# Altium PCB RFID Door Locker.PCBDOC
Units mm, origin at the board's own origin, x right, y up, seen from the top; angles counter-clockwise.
Board outline 386.33 x 171.7 mm, 2 copper layers (TopLayer, BottomLayer); 61 components, 0 nets, 248 pads, 41 vias.
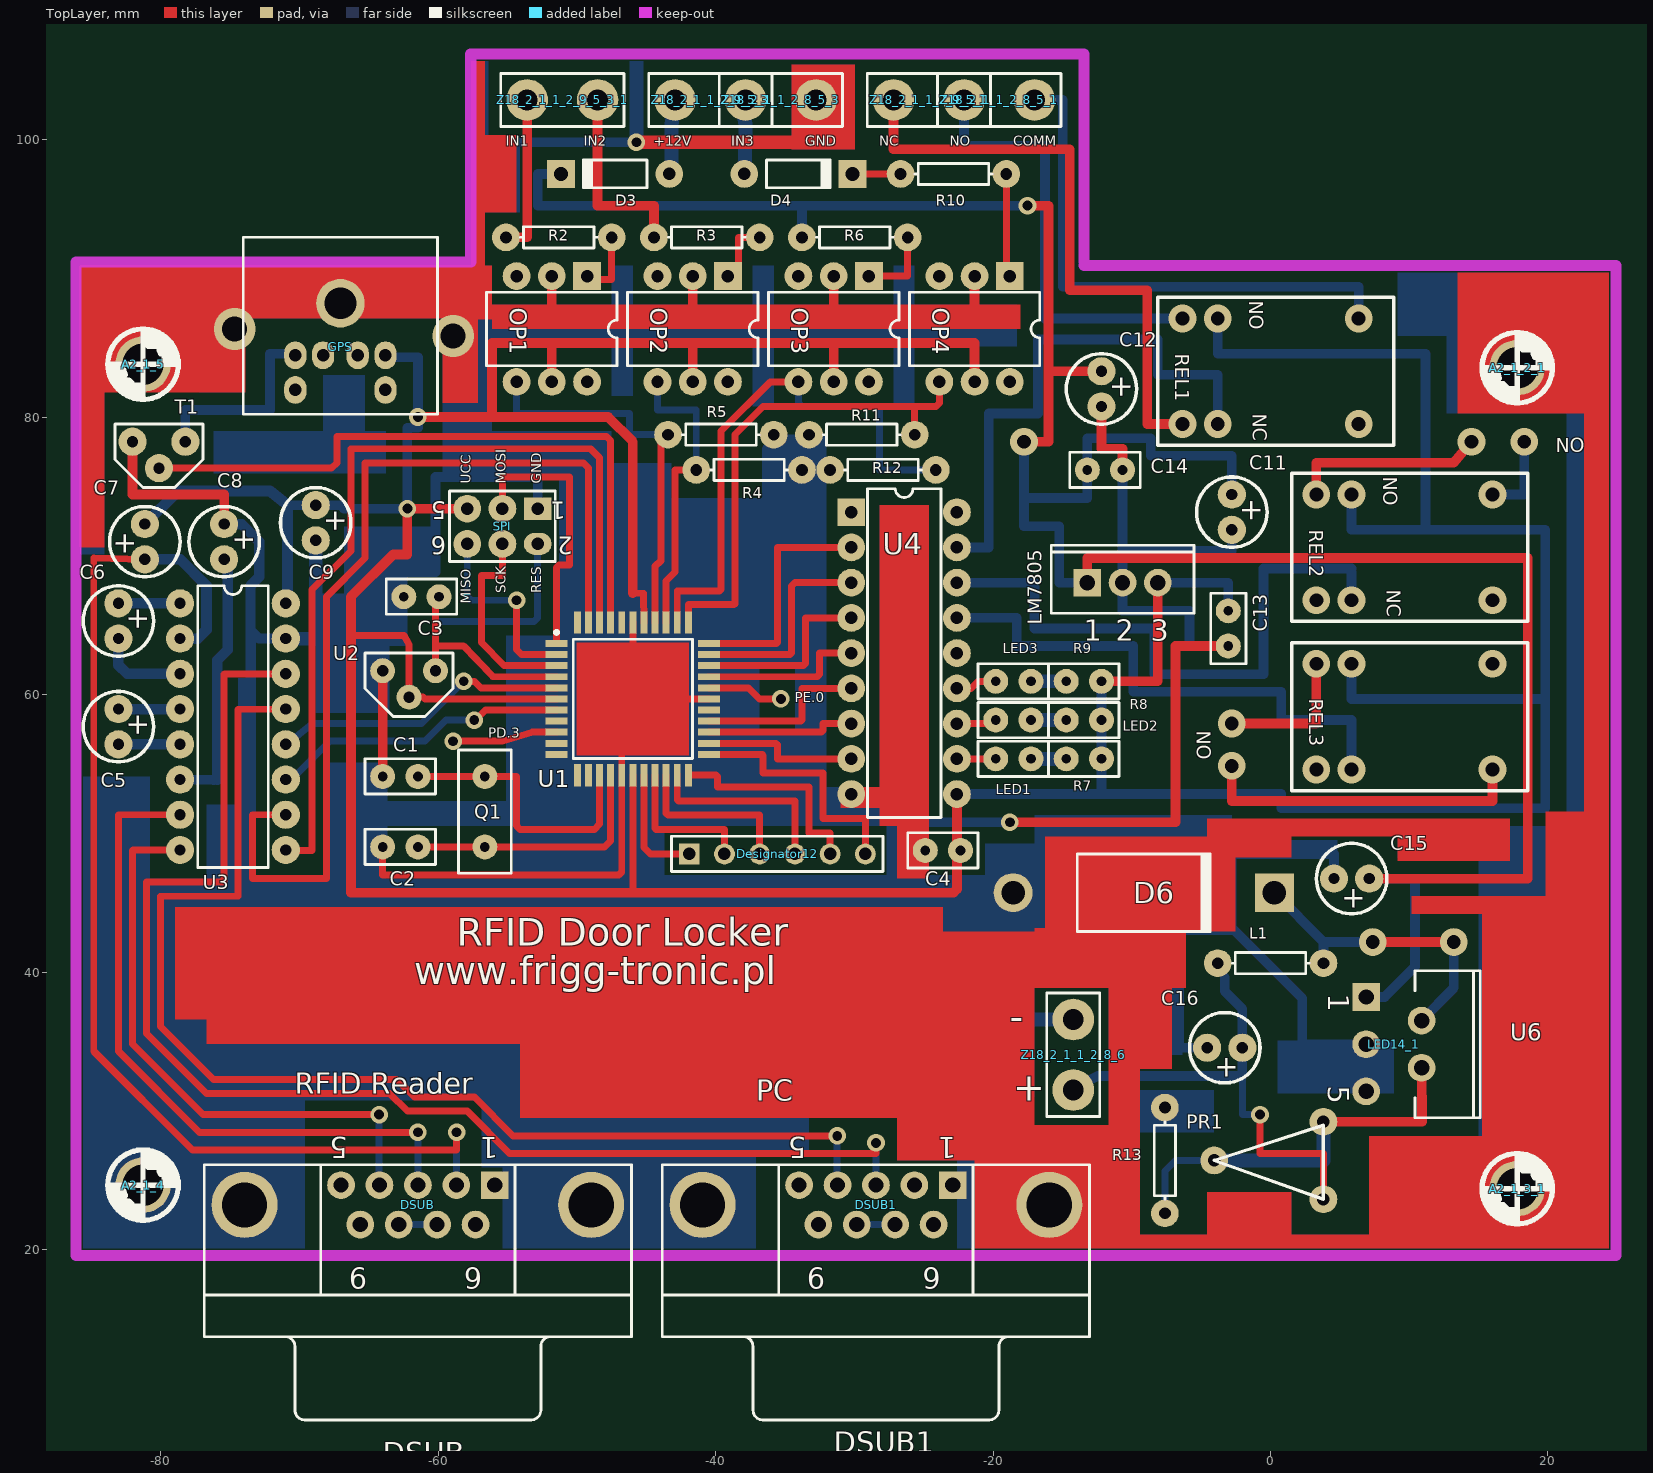
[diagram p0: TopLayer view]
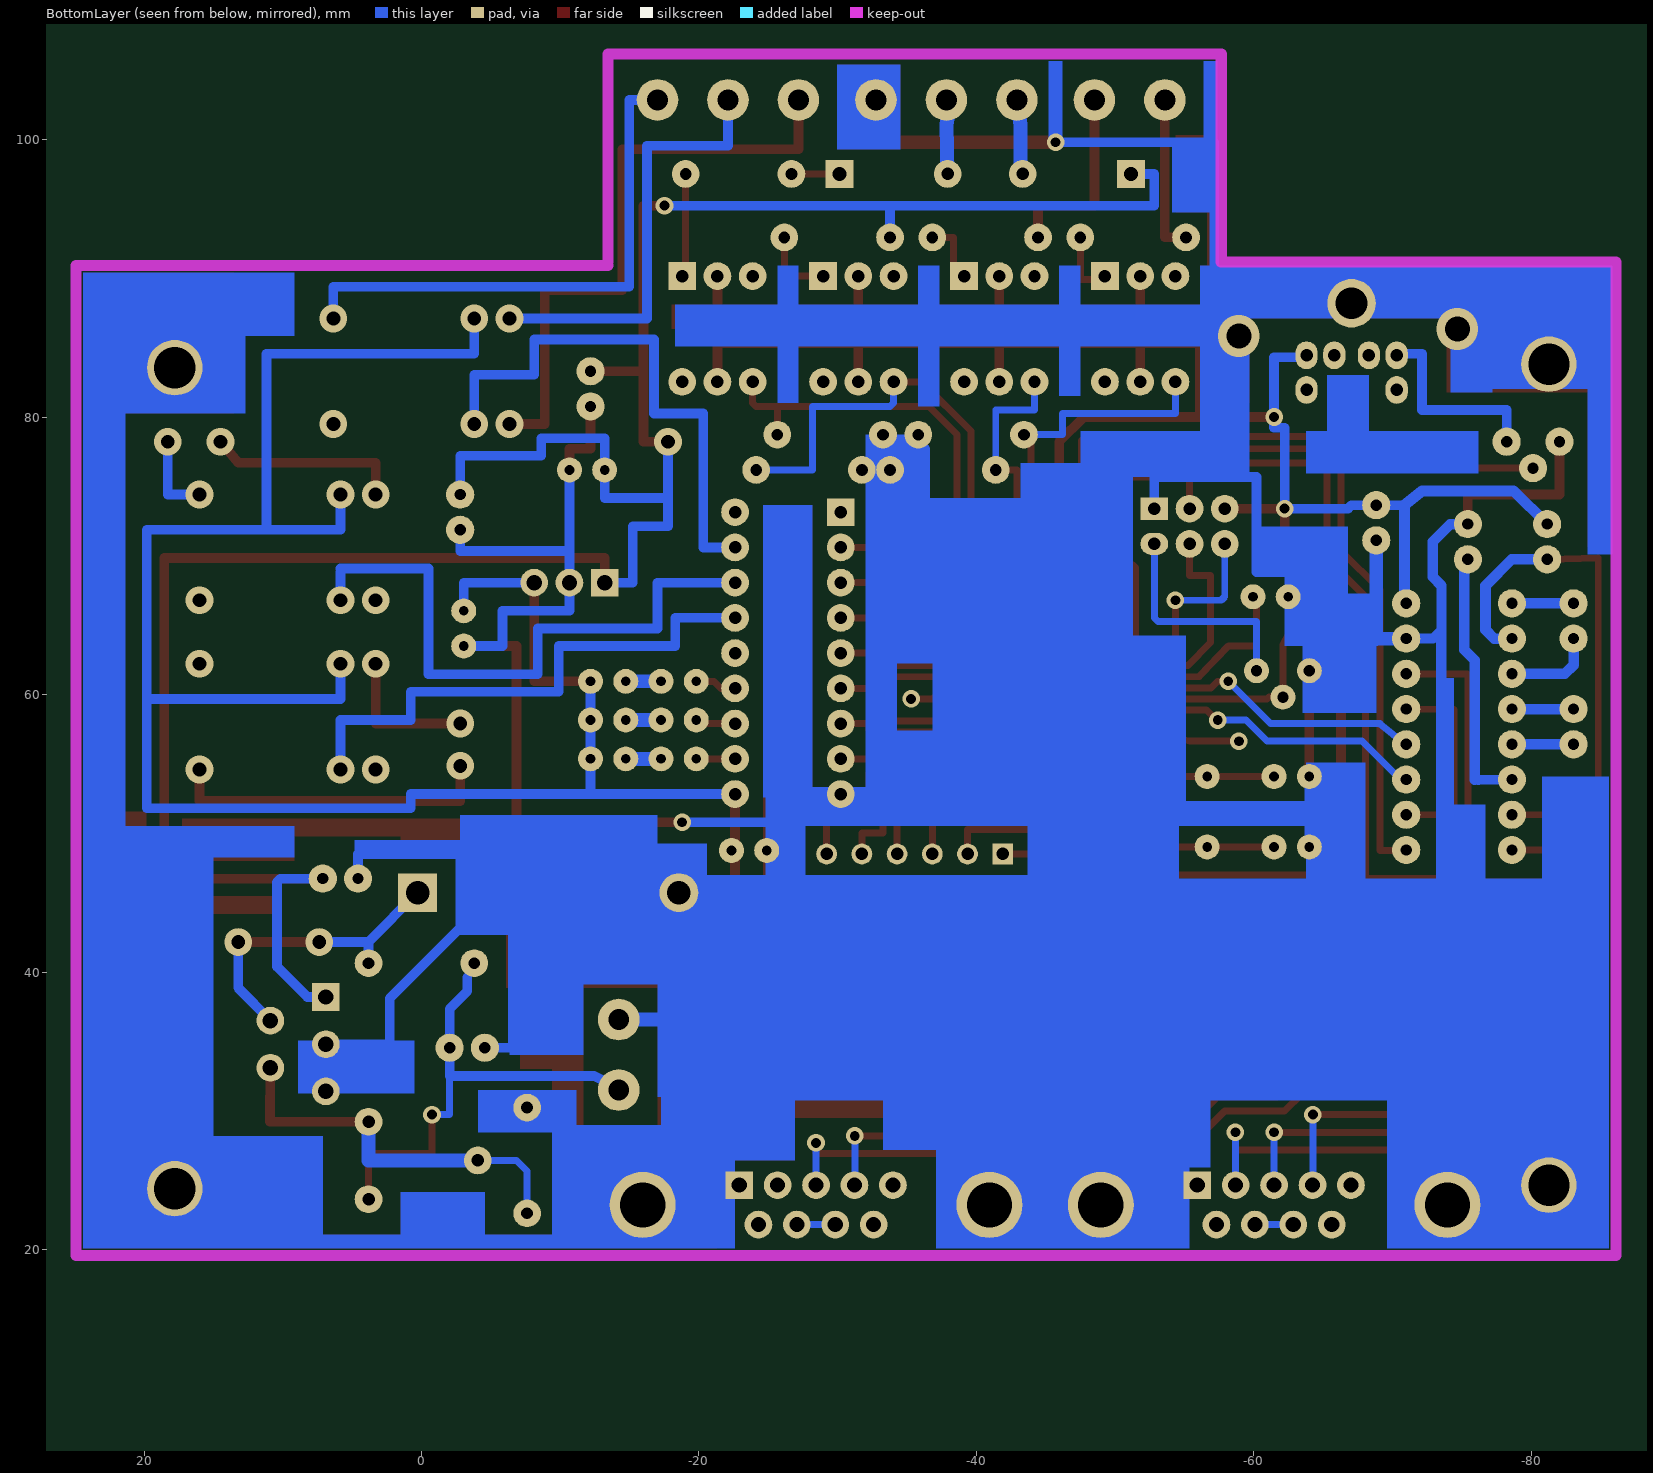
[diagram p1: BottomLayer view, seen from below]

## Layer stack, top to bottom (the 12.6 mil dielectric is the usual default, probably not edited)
TopLayer: signal copper 0.0356
Dielectric: core 0.32, FR-4, Dk 4.8
BottomLayer: signal copper 0.0356

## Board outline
-121.158,136.652 -121.158,-35.052 265.176,-35.052 265.176,136.652

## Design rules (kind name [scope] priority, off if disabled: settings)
Clearance [All] p1: gap=1
ComponentClearance [All] p1: gap=0.254 collisioncheckmode=0
PasteMaskExpansion PasteMaskExpansion_1 [All] p2: expansion=0
PlaneClearance PlaneClearance_1 [All] p1: clearance=0.508
PlaneClearance [All] p2: clearance=0.254
PolygonConnect [All] p1: connectstyle=Relief reliefconductorwidth=0.254 reliefentries=4 polygonreliefangle="90 Angle"
RoutingVias [All] p1: holewidth=1 width=3 viastyle="Through Hole" minholewidth=0.711 minwidth=1.27 maxholewidth=0.711 maxwidth=1.27
ShortCircuit ShortCircuit_1 [All] p2: allowed=FALSE
SolderMaskExpansion SolderMaskExpansion_1 [All] p1: expansion=0.102
SolderMaskExpansion [All] p2: expansion=0.051
TestPointUsage [All] p1: valid=0 allowmultiple=FALSE
Testpoint [All] p1: side=7 testpointundercomponent=TRUE minsize=1.016 maxsize=2.54 preferedsize=1.524 minholesize=0.508 maxholesize=1.016 preferedholesize=0.813 testpointgrid=0.025 style=1001 order=1234567890
UnRoutedNet UnRoutedNet_1 [All] p2:
Width [All] p1: maxlimit=0.8 minlimit=0.1 preferedwidth=0.254 toplayer_maxwidth=0.7 toplayer_prefwidth=0.5 bottomlayer_maxwidth=0.7 bottomlayer_prefwidth=0.5 minimp=50.000000 maximp=50.000000 favimp=50.000000
16 further rules are at their usual default settings.

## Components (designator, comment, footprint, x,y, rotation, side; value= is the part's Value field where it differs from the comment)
A2_1_2_1 "" S2 17.78,83.566 r0 top
A2_1_3_1 "" S2 17.78,24.384 r0 top
A2_1_4 "" S2 -81.28,24.638 r0 top
A2_1_5 "" S2 -81.28,83.82 r0 top
C1 "Comment" RAD-0.1 -61.468,54.102 r180 top
C2 "Comment" RAD-0.1 -61.468,49.022 r180 top
C3 "Comment" RAD-0.1 -59.944,67.056 r180 top
C4 "Comment" RAD-0.1 -22.352,48.768 r180 top
C5 "" CE5#1 -83.058,58.959 r270 top
C6 "" CE5#1 -83.058,66.579 r270 top locked
C7 "" CE5#2 -81.153,69.754 r270 top
C8 "" CE5#1 -75.438,72.294 r270 top locked
C9 "" CE5#1 -68.834,73.66 r270 top
C11 "" CE5#2 -2.794,74.422 r90 top
C12 "" CE5#2 -12.192,83.312 r90 top
C13 "Comment" RAD-0.1 -3.048,66.04 r270 top
C14 "Comment" RAD-0.1 -10.668,76.2 r180 top
C15 "" CE5#1 7.112,46.736 r180 top
C16 "" CE5#1 -2.032,34.544 r180 top
D3 "Comment" DIO7.8-4.6x2 -47.244,97.536 r180 top
D4 "Comment" DIO7.8-4.6x2 -34.036,97.536 r0 top
D6 "Comment" DIO18.84-9.6x5.6 -9.144,45.72 r0 top
Designator12 "Comment" HDR1X6 -41.91,48.514 r0 top
DSUB "Comment" DSUB1.385-2H9 -61.468,13.716 r180 top
DSUB1 "Comment" DSUB1.385-2H9 -28.448,13.716 r180 top
GPS "Comment" PS2-6PIN -67.056,92.964 r0 top
L1 "Comment" AXIAL-0.3 0,40.64 r0 top
LED1 "Comment" RAD-0.1 -17.272,55.372 r180 top
LED2 "Comment" RAD-0.1 -17.272,58.166 r180 top
LED3 "Comment" RAD-0.1 -17.272,60.96 r180 top
LED14_1 "Comment" T05D 8.89,34.798 r270 top
LM7805 "Comment" SFM-T3/X1.6V -10.668,68.072 r0 top
OP1 "Comment" DIP-6 -51.816,86.36 r180 top
OP2 "Comment" DIP-6 -41.656,86.36 r180 top
OP3 "Comment" DIP-6 -31.496,86.36 r180 top
OP4 "Comment" DIP-6 -21.336,86.36 r180 top
Q1 "Comment" RAD-0.2#1 -56.642,54.102 r270 top
R2 "Comment" AXIAL-0.3 -51.308,92.964 r0 top
R3 "Comment" AXIAL-0.3 -40.64,92.964 r0 top
R4 "Comment" AXIAL-0.3 -37.592,76.2 r0 top
R5 "Comment" AXIAL-0.3 -39.624,78.74 r0 top
R6 "Comment" AXIAL-0.3 -29.972,92.964 r0 top
R7 "Comment" RAD-0.1 -12.192,55.372 r180 top
R8 "Comment" RAD-0.1 -12.192,58.166 r180 top
R9 "Comment" RAD-0.1 -12.192,60.96 r180 top
R10 "Comment" AXIAL-0.3 -22.86,97.536 r0 top
R11 "Comment" AXIAL-0.3 -29.464,78.74 r0 top
R12 "Comment" AXIAL-0.3 -27.94,76.2 r180 top
R13 "Comment" AXIAL-0.3 -7.62,26.416 r90 top
SPI "Comment" HDR2X3 -52.832,73.406 r180 top
T1 "" T#1 -82.042,78.232 r0 top
U1 "Comment" 44A -45.974,59.69 r0 top
U2 "" T#2 -64.008,61.722 r0 top
U3 "" U16 -78.613,66.579 r270 top locked
U4 "Comment" DIP-18 -26.416,62.992 r270 top
Z18_2_1_1_2_8_5_1 "Comment" RAD-0.2#2 -17.018,102.87 r180 top
Z18_2_1_1_2_8_5_3 "Comment" RAD-0.2#2 -32.766,102.87 r180 top
Z18_2_1_1_2_8_6 "Comment" RAD-0.2#2 -14.224,36.576 r270 top
Z18_2_1_1_2_9_5_1 "Comment" RAD-0.2#2 -22.098,102.87 r180 top
Z18_2_1_1_2_9_5_3 "Comment" RAD-0.2#2 -37.846,102.87 r180 top
Z18_2_1_1_2_9_5_3_1 "Comment" RAD-0.2#2 -48.514,102.87 r180 top

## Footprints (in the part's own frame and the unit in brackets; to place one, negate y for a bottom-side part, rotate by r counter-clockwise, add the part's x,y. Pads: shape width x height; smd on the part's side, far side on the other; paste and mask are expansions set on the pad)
44A [mm] "QFP; 44 Leads; Body 10 x 10 mm; Pitch 0.8 mm"
  rect 1.6x0.5 smd: 1(-5.5,4) 2(-5.5,3.2) 3(-5.5,2.4) 4(-5.5,1.6) 5(-5.5,0.8) 6(-5.5,0) 7(-5.5,-0.8) 8(-5.5,-1.6) 9(-5.5,-2.4) 10(-5.5,-3.2) 11(-5.5,-4) 23(5.5,-4) 24(5.5,-3.2) 25(5.5,-2.4) 26(5.5,-1.6) 27(5.5,-0.8) 28(5.5,0) 29(5.5,0.8) 30(5.5,1.6) 31(5.5,2.4) 32(5.5,3.2) 33(5.5,4)
  rect 0.5x1.6 smd: 12(-4,-5.5) 13(-3.2,-5.5) 14(-2.4,-5.5) 15(-1.6,-5.5) 16(-0.8,-5.5) 17(0,-5.5) 18(0.8,-5.5) 19(1.6,-5.5) 20(2.4,-5.5) 21(3.2,-5.5) 22(4,-5.5) 34(4,5.5) 35(3.2,5.5) 36(2.4,5.5) 37(1.6,5.5) 38(0.8,5.5) 39(0,5.5) 40(-0.8,5.5) 41(-1.6,5.5) 42(-2.4,5.5) 43(-3.2,5.5) 44(-4,5.5)
  silkscreen extent -5.62,-4.3 4.3,4.92
AXIAL-0.3 [mm]
  round 2 hole 0.85: 1(-3.81,0) 2(3.81,0)
  silkscreen extent -2.77,-0.76 2.77,0.76
CE5#1 [mil]
  round 80 hole 32: 1(0,0) 2(100,0)
  silkscreen extent -50,-100 150,100
CE5#2 [mil]
  round 80 hole 32: 1(0,0) 2(-100,0)
  silkscreen extent -150,-100 50,100
DIO7.8-4.6x2 [mm]
  round 2 hole 0.9: 1(-3.9,0)
  rect 2x2 hole 1: 2(3.9,0)
  silkscreen extent -2.3,-1 2.4,1
DIO18.84-9.6x5.6 [mm]
  round 2.8 hole 1.7: 1(-9.42,0)
  rect 2.8x2.8 hole 1.7: 2(9.42,0)
  silkscreen extent -4.8,-2.8 4.9,2.8
DIP-6 [mm]
  rect 2x2 hole 0.9: 1(-2.54,-3.81)
  round 2 hole 0.9: 2(0,-3.81) 3(2.54,-3.81) 4(2.54,3.81) 5(0,3.81) 6(-2.54,3.81)
  silkscreen extent -4.7,-2.65 4.7,2.65
DIP-18 [mm]
  rect 2x2 hole 0.9: 1(-10.16,-3.81)
  round 2 hole 0.9: 2(-7.62,-3.81) 3(-5.08,-3.81) 4(-2.54,-3.81) 5(0,-3.81) 6(2.54,-3.81) 7(5.08,-3.81) 8(7.62,-3.81) 9(10.16,-3.81) 10(10.16,3.81) 11(7.62,3.81) 12(5.08,3.81) 13(2.54,3.81) 14(0,3.81) 15(-2.54,3.81) 16(-5.08,3.81) 17(-7.62,3.81) 18(-10.16,3.81)
  silkscreen extent -11.85,-2.65 11.85,2.65
DSUB1.385-2H9 [mm] "Connector; D Subminiature; 9 Position; Right Angle; Pitch 1.385 mm"
  round 2 hole 1.09: 1(5.54,-10.92) 2(2.77,-10.92) 3(0,-10.92) 4(-2.77,-10.92) 6(4.155,-8.08) 7(1.385,-8.08) 8(-1.385,-8.08) 9(-4.155,-8.08)
  rect 2x2 hole 1.09 unplated: 5(-5.54,-10.92)
  round 4.76 hole 3.26: 10(-12.495,-9.5) 11(12.495,-9.5)
  silkscreen extent -15.4,-12.4 15.4,6
HDR1X6 [mm] "Connector; Header; 6 Position"
  rect 1.5x1.5 hole 0.9: 1(0,0)
  round 1.5 hole 0.9: 2(2.54,0) 3(5.08,0) 4(7.62,0) 5(10.16,0) 6(12.7,0)
  silkscreen extent -1.27,-1.27 13.97,1.27
HDR2X3 [mm]
  rect 2x1.6 hole 0.9: 1(0,0)
  oval 2x1.6 hole 0.9: 2(0,2.54)
  round 2 hole 0.9: 3(2.54,0) 4(2.54,2.54) 5(5.08,0) 6(5.08,2.54)
  silkscreen extent -1.27,-1.27 6.35,3.81
PS2-6PIN [mm] "PS2 Socket, 6 Pin, Through Hole"
  oval 1.6x2 hole 0.9: 1(-1.25,-8.5) 2(1.25,-8.5) 3(-3.25,-8.5) 4(3.25,-8.5) 5(-3.25,-11) 6(3.25,-11)
  round 3.5 hole 2.3: S(0,-4.75)
  silkscreen extent -7,-12.75 7,0
RAD-0.1 [mm]
  round 1.8 hole 0.7: 1(0,0) 2(2.54,0)
  silkscreen extent -1.27,-1.27 3.81,1.27
RAD-0.2#1 [mm]
  round 1.8 hole 0.7: 1(0,0) 2(5.08,0)
  silkscreen extent -1.91,-1.91 6.98,1.91
RAD-0.2#2 [mm]
  round 3 hole 1.5: 1(0,0) 2(5.08,0)
  silkscreen extent -1.91,-1.91 6.98,1.91
S2 [mm]
  round 4 hole 2.972: 0(0,0)
  silkscreen extent -2.54,-2.54 2.54,2.54
SFM-T3/X1.6V [mm]
  rect 2x2 hole 1.1: 1(-2.54,0)
  round 2 hole 1.1: 2(0,0) 3(2.54,0)
  silkscreen extent -5.15,-2.2 5.15,2.7
T#1 [mil]
  round 80 hole 32: 1(0,0) 2(75,-75) 3(150,0)
  silkscreen extent -50,-130 200,50
T#2 [mil]
  round 70.87 hole 32: 1(0,0) 2(75,-75) 3(150,0)
  silkscreen extent -50,-130 200,50
T05D [mm] "TO, Thru-Hole, Vertical, Heatsink Mounted; 5 Bent Staggered Leads; Pitch 1.7 mm"
  rect 2x2 hole 1.1: 1(-3.4,-2)
  round 2 hole 1.1: 2(-1.7,2) 3(0,-2) 4(1.7,2) 5(3.4,-2)
  silkscreen extent -5.3,1.53 5.3,6.23
U16 [mil]
  round 80 hole 32: 1(0,0) 2(100,0) 3(200,0) 4(300,0) 5(400,0) 6(500,0) 7(600,0) 8(700,0) 9(700,300) 10(600,300) 11(500,300) 12(400,300) 13(300,300) 14(200,300) 15(100,300) 16(0,300)
  silkscreen extent -50,50 750,250

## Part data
D6: library part "Diode 1N5402"
Designator12: library part "Header 6"
DSUB DSUB1: library part "D Connector 9"
GPS: library part PS2-6PIN
LED14_1: library part LM2576HVT-5.0LB03
LM7805: library part Diac-NPN
SPI: library part "Header 3X2"
U1: library part ATmega162-16AC

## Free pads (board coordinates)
  round 2 hole 1: 0(7.366,42.164) 0(13.208,42.164)
  round 2 hole 0.9: 9(-4.064,26.416) 10(3.81,29.21) 11(3.81,23.622)

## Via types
v1: diameter 2, hole 1, TopLayer to BottomLayer, 23 vias
v2: diameter 1.27, hole 0.711, TopLayer to BottomLayer, 16 vias
v3: diameter 3, hole 1.8, TopLayer to BottomLayer, 2 vias

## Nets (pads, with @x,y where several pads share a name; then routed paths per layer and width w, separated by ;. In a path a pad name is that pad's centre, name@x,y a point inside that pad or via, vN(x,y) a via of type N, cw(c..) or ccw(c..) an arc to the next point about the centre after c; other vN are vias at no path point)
pads on no net: A2_1_2_1.0 A2_1_3_1.0 A2_1_4.0 A2_1_5.0 C1.1 C1.2 C2.1 C2.2 C3.1 C3.2 C4.1 C4.2 C5.1 C5.2 C6.1 C6.2 C7.1 C7.2 C8.1 C8.2 C9.1 C9.2 C11.1 C11.2 C12.1 C12.2 C13.1 C13.2 C14.1 C14.2 C15.1 C15.2 C16.1 C16.2 D3.1 D3.2 D4.1 D4.2 D6.1 D6.2 Designator12.1 Designator12.2 Designator12.3 Designator12.4 Designator12.5 Designator12.6 DSUB1.1 DSUB1.2 DSUB1.3 DSUB1.4 DSUB1.5 DSUB1.6 DSUB1.7 DSUB1.8 DSUB1.9 DSUB1.10 DSUB1.11 DSUB.1 DSUB.2 DSUB.3 DSUB.4 DSUB.5 DSUB.6 DSUB.7 DSUB.8 DSUB.9 DSUB.10 DSUB.11 GPS.1 GPS.2 GPS.3 GPS.4 GPS.5 GPS.6 GPS.S L1.1 L1.2 LED1.1 LED1.2 LED2.1 LED2.2 LED3.1 LED3.2 LED14_1.1 LED14_1.2 LED14_1.3 LED14_1.4 LED14_1.5 LM7805.1 LM7805.2 LM7805.3 OP1.1 OP1.2 OP1.3 OP1.4 OP1.5 OP1.6 OP2.1 OP2.2 OP2.3 OP2.4 OP2.5 OP2.6 OP3.1 OP3.2 OP3.3 OP3.4 OP3.5 OP3.6 OP4.1 OP4.2 OP4.3 OP4.4 OP4.5 OP4.6 Q1.1 Q1.2 R2.1 R2.2 R3.1 R3.2 R4.1 R4.2 R5.1 R5.2 R6.1 R6.2 R7.1 R7.2 R8.1 R8.2 R9.1 R9.2 R10.1 R10.2 R11.1 R11.2 R12.1 R12.2 R13.1 R13.2 SPI.1 SPI.2 SPI.3 SPI.4 SPI.5 SPI.6 T1.1 T1.2 T1.3 U1.1 U1.2 U1.3 U1.4 U1.5 U1.6 U1.7 U1.8 U1.9 U1.10 U1.11 U1.12 U1.13 U1.14 U1.15 U1.16 U1.17 U1.18 U1.19 U1.20 U1.21 U1.22 U1.23 U1.24 U1.25 U1.26 U1.27 U1.28 U1.29 U1.30 U1.31 U1.32 U1.33 U1.34 U1.35 U1.36 U1.37 U1.38 U1.39 U1.40 U1.41 U1.42 U1.43 U1.44 U2.1 U2.2 U2.3 U3.1 U3.2 U3.3 U3.4 U3.5 U3.6 U3.7 U3.8 U3.9 U3.10 U3.11 U3.12 U3.13 U3.14 U3.15 U3.16 U4.1 U4.2 U4.3 U4.4 U4.5 U4.6 U4.7 U4.8 U4.9 U4.10 U4.11 U4.12 U4.13 U4.14 U4.15 U4.16 U4.17 U4.18 Z18_2_1_1_2_8_5_1.1 Z18_2_1_1_2_8_5_1.2 Z18_2_1_1_2_8_5_3.1 Z18_2_1_1_2_8_5_3.2 Z18_2_1_1_2_8_6.1 Z18_2_1_1_2_8_6.2 Z18_2_1_1_2_9_5_1.1 Z18_2_1_1_2_9_5_1.2 Z18_2_1_1_2_9_5_3.1 Z18_2_1_1_2_9_5_3.2 Z18_2_1_1_2_9_5_3_1.1 Z18_2_1_1_2_9_5_3_1.2
copper on no net: | length 2482.1
  TopLayer w0.5: -81.153,69.754 -84.836,69.85 -84.836,47.752 -84.836,46.736 -84.836,34.29 -77.724,27.178 -58.674,27.178 v2(-58.674,28.448) ; -80.137,76.327 -68.199,76.327 -67.691,76.327 -67.31,76.708 -67.31,78.613 -47.879,78.613 -47.574,78.308 -47.574,65.19 ; -78.613,48.799 -82.011,48.799 -82.042,48.768 -82.042,34.798 -76.962,29.718 v2(-64.262,29.718) ; -78.613,51.339 -83.027,51.339 -83.058,51.308 -83.058,34.29 -77.216,28.448 v2(-61.468,28.448) ; -70.993,48.799 -70.358,48.768 -69.088,48.768 -69.088,49.53 -69.088,51.816 -69.088,67.564 -66.294,70.358 -66.294,71.12 -66.294,77.724 -54.864,77.724 ; -70.993,51.339 -73.375,51.339 -73.406,51.308 -73.406,46.736 -73.152,46.736 -68.072,46.736 -68.072,47.752 -68.072,55.372 -68.072,67.056 -65.278,69.85 -65.278,71.12 -65.278,76.708 -49.53,76.708 -49.174,76.352 -49.174,65.19 ; -70.993,58.959 -74.422,58.928 -74.422,55.626 -74.422,45.466 -80.01,45.466 -80.01,36.068 -76.2,32.258 -62.992,32.258 -61.722,30.988 -57.404,30.988 -54.61,28.194 v2(-31.242,28.194) ; -70.993,61.499 -75.407,61.499 -75.438,61.468 -75.438,46.482 -81.026,46.482 -81.026,35.56 -76.708,31.242 -63.5,31.242 -62.23,29.972 -57.912,29.972 -54.864,26.924 -28.448,26.924 v2(-28.448,27.686) ; -66.294,64.262 -62.738,64.262 -62.484,64.262 -62.103,63.627 -62.103,59.817 -61.087,59.817 -60.96,59.69 -59.182,59.69 -51.474,59.69 ; -64.008,49.022 -64.008,46.99 -54.864,46.99 -46.99,46.99 -46.774,47.206 -46.774,47.282 -46.774,51.854 -46.774,54.19 -46.774,55.842 ; -61.722,49.022 -56.642,49.022 -48.006,49.022 -47.574,49.454 -47.574,50.622 -47.574,54.19 ; -61.468,54.102 -56.642,54.102 -55.118,54.102 -54.356,54.102 -54.356,50.546 -54.102,50.292 -48.742,50.292 -48.374,50.66 -48.374,54.19 ; -60.198,61.722 -60.198,63.754 -60.198,64.262 -60.198,66.294 -59.944,67.056 ; -60.198,63.5 -58.166,63.5 -56.134,61.366 -56.058,61.29 -51.474,61.29 ; v2(-58.928,56.642) -55.372,56.642 -53.226,57.29 -51.474,57.29 ; v3(-58.928,85.852) v3@-57.912,85.852 ; v2(-58.166,60.96) -57.404,60.96 -56.934,60.49 -51.474,60.49 ; v2(-57.404,58.166) -57.328,58.166 -56.604,58.89 -51.474,58.89 ; -55.372,70.866 -55.372,68.58 -56.896,68.58 -56.896,66.04 -56.896,63.754 -55.258,62.09 -51.474,62.09 ; -55.372,73.406 -55.372,75.692 -50.546,75.692 -50.546,69.342 -51.308,69.342 -51.474,69.176 -51.474,63.69 ; -55.118,77.724 -49.022,77.724 -48.374,77.076 -48.374,76.314 -48.374,65.19 ; v2(-54.356,66.802) -54.356,63.246 -54,62.89 -51.474,62.89 ; -49.022,89.916 -48.514,89.916 -47.498,89.916 -47.498,90.932 -47.498,92.964 ; -45.974,45.72 -45.974,54.19 ; -45.974,63.246 -45.974,65.19 ; -45.974,67.31 -45.212,67.31 -45.174,65.19 ; -45.174,54.19 -45.174,48.984 -44.704,48.514 -41.91,48.514 ; -44.374,54.19 -44.374,50.368 -44.298,50.292 -39.37,50.292 -39.37,48.514 ; -44.374,65.19 -44.374,69.266 -43.942,69.646 -43.942,78.74 ; -43.574,54.19 -43.574,51.448 -43.434,51.308 -36.83,51.308 -36.83,48.514 ; -43.574,65.19 -43.574,68.186 -42.926,68.834 -42.926,73.152 -42.926,76.2 -41.402,76.2 ; -43.344,97.192 -43.344,97.536 ; -42.774,54.19 -42.774,52.426 -42.672,52.324 -34.29,52.324 -34.29,48.514 ; -42.774,65.19 -42.774,67.208 -42.774,67.462 -39.726,67.462 ; -42.164,59.69 -40.474,59.69 ; -41.974,54.19 -39.966,54.19 -39.878,54.102 -39.878,53.34 -33.274,53.34 -33.274,50.038 -31.75,50.038 -31.75,48.514 -31.838,48.602 ; -41.974,65.19 -41.974,66.484 -38.672,66.484 -38.608,66.548 -38.608,69.85 -38.608,72.136 -38.608,78.74 -36.576,80.772 -24.13,80.772 -23.876,81.026 -23.876,82.55 ; -40.474,55.69 -38.164,55.69 -36.64,55.69 -36.576,55.626 -36.576,54.356 -32.258,54.356 -32.258,51.054 -29.21,51.054 -29.21,48.514 ; -40.474,56.49 -35.662,56.49 -35.56,56.388 -35.56,55.372 -30.226,55.372 ; -40.474,57.29 -32.372,57.29 -32.258,57.404 -32.258,57.912 -30.226,57.912 ; -40.474,58.09 -33.858,58.09 -33.782,58.166 -33.782,60.452 -33.274,60.452 -30.226,60.452 ; -40.474,60.49 -37.63,60.49 -36.83,59.69 v2(-35.306,59.69) ; -40.474,61.29 -32.69,61.29 -32.512,61.468 -32.512,62.992 -30.226,62.992 ; -40.474,62.09 -36.97,62.09 -33.668,62.09 -33.528,62.23 -33.528,65.532 -30.226,65.532 ; -40.474,62.89 -34.646,62.89 -34.544,62.992 -34.544,67.818 -34.29,68.072 -30.226,68.072 ; -40.474,63.69 -35.624,63.69 -35.56,63.754 -35.56,70.612 -30.226,70.612 ; -39.624,67.564 -39.624,70.612 -39.624,72.136 -39.624,78.994 -36.068,82.55 -34.036,82.55 ; -38.354,89.916 -38.354,92.964 -37.592,92.964 -36.83,92.964 ; -30.136,97.536 -26.924,97.536 -26.924,97.282 ; -28.956,90.17 -27.432,90.17 -26.162,90.17 -26.162,91.44 -26.162,92.964 ; -25.654,78.74 -25.654,80.772 ; -22.606,55.372 -19.812,55.372 ; -22.606,57.912 -20.066,57.912 -19.812,58.166 ; -22.606,60.452 -21.59,60.452 -21.082,60.96 -19.812,60.96 ; -19.05,97.536 -19.05,94.234 -19.05,91.186 -18.796,90.17 ; v2(-0.762,29.718) -0.762,26.924 3.81,26.924 3.81,23.622
  TopLayer w0.7: -82.042,78.232 -82.042,74.422 -75.438,74.422 -75.438,72.294 ; -64.008,54.102 -64.008,61.722 ; v2(-61.468,80.01) -48.768,80.01 -47.752,80.01 -45.974,78.232 -45.974,67.31 ; v3(-58.928,85.852) -57.912,87.376 -51.816,87.376 ; -57.912,73.406 v2(-62.23,73.406) -62.23,70.104 -63.246,70.104 -66.294,67.056 -66.294,46.736 -66.294,45.72 -45.974,45.72 -22.86,45.72 -22.606,45.974 -22.606,52.832 ; -56.134,80.01 -56.134,85.344 -51.816,85.344 ; -55.118,92.964 -53.594,92.964 -53.594,102.87 ; -51.816,82.55 -51.816,85.344 ; -51.816,90.17 -51.816,87.376 ; -48.514,102.87 -48.514,95.25 -44.45,95.25 -44.45,92.964 ; -41.656,82.55 -41.656,85.344 ; -41.656,90.17 -41.656,87.376 ; -40.894,87.376 -41.656,87.376 ; -31.496,82.55 -31.496,85.344 ; -31.496,90.17 -31.496,87.376 ; -27.178,102.87 -27.178,99.314 -14.478,99.314 -14.478,89.154 -8.89,89.154 -8.89,79.502 v1(-6.35,79.502) ; -21.336,82.55 -21.336,85.344 -31.496,85.344 ; -21.336,90.17 -21.336,87.376 -31.496,87.376 ; v2(-18.796,50.8) -6.858,50.8 -6.858,63.5 -3.048,63.5 ; v1(-17.78,78.232) -16.002,78.232 -16.002,83.312 ; v2(-17.526,95.25) -16.002,95.25 -16.002,88.646 -16.002,83.312 ; -13.208,68.072 -13.208,69.85 8.636,69.85 18.542,69.85 18.542,46.736 7.112,46.736 ; -12.192,60.96 -8.128,60.96 -8.128,68.072 ; -12.192,80.772 -12.192,77.978 -12.192,77.724 -10.668,77.724 -10.668,76.2 ; -12.192,83.312 -16.002,83.312 ; v1(-2.794,54.864) -2.794,52.324 16.002,52.324 v1(16.002,54.61) ; v1(-2.794,57.912) 3.302,57.912 v1(3.302,62.23) ; v1(3.302,74.422) 3.302,76.708 13.208,76.708 v1(14.478,78.232) ; 3.81,29.21 10.922,29.21 10.89,33.098 ; 7.366,42.164 13.208,42.164 ; -51.816,85.344 -41.656,85.344 ; -51.816,87.376 -41.656,87.376 ; -41.656,85.344 -31.496,85.344 ; -41.656,87.376 -31.496,87.376
  TopLayer w1: v2(-45.72,99.822) -32.766,99.822 -32.766,102.87
  BottomLayer w0.5: -70.993,56.419 -70.962,56.388 -69.088,57.912 -64.262,57.912 -61.214,57.912 v2(-58.166,60.96) ; -70.358,54.102 -67.818,56.642 -60.96,56.642 -59.436,58.166 v2(-57.404,58.166) ; -64.262,24.66 v2(-64.262,29.718) ; -62.853,21.796 -60.083,21.796 ; -61.468,24.636 v2(-61.468,28.448) ; -60.198,61.722 -60.198,65.278 -53.086,65.278 -52.832,65.532 -52.832,70.866 ; -58.698,24.636 -58.674,24.66 v2(-58.674,28.448) ; -57.912,70.866 -57.912,67.056 -57.658,66.802 v2(-54.356,66.802) ; -54.356,82.55 -54.356,80.264 -46.228,80.264 -46.228,78.74 -43.942,78.74 ; -44.196,82.55 -44.196,80.518 -41.402,80.518 -41.402,78.74 -41.402,76.2 ; -38.1,102.616 -37.846,102.87 ; -34.036,82.55 -34.036,81.026 -33.782,80.772 -28.194,80.772 -28.194,76.2 -24.13,76.2 ; -31.242,24.66 v2(-31.242,28.194) ; -29.833,21.796 -27.063,21.796 ; -28.448,24.636 v2(-28.448,27.686) ; -7.62,22.098 -7.62,25.654 -6.858,26.416 -4.572,26.416 -4.064,26.416 ; -2.032,32.512 -2.032,29.718 v2(-0.762,29.718)
  BottomLayer w0.7: -81.311,72.136 -81.153,72.294 ; -78.836,51.562 -78.613,51.339 ; -78.613,53.879 -76.2,53.848 ; -78.232,78.232 -78.232,80.518 -72.136,80.518 -72.136,84.582 -71.12,84.582 -70.306,84.464 ; -73.533,67.849 -73.533,64.643 -72.929,64.039 -70.993,64.039 ; -70.993,48.799 -70.866,49.022 ; -70.866,73.66 -68.834,73.66 -67.056,73.66 -66.802,73.406 v2(-62.23,73.406) -62.23,79.248 -61.468,79.248 -61.468,84.328 -63.246,84.328 -63.806,84.464 ; -64.008,49.022 -64.008,54.102 ; -64.008,61.722 -64.008,63.5 ; -62.992,66.802 -62.992,68.834 -60.198,68.834 -60.198,75.692 -52.832,75.692 -52.832,73.406 ; -57.15,90.678 -57.15,99.822 v2(-45.72,99.822) ; -56.896,49.022 -56.582,49.082 ; -51.144,97.536 -52.832,97.536 -52.832,95.25 -33.782,95.25 ; -48.006,71.12 -36.322,71.12 -36.322,73.914 ; -36.322,77.724 -36.322,73.66 -36.322,75.184 -33.782,75.184 -33.782,72.644 ; -33.782,92.964 -33.782,95.25 ; -30.226,52.832 -25.146,52.832 -25.146,51.308 -25.146,46.736 ; -25.146,50.8 v2(-18.796,50.8) ; -22.606,52.832 -12.192,52.832 ; -22.606,65.532 -18.288,65.532 -18.288,63.5 -9.906,63.5 -9.906,60.198 0.762,60.198 0.762,58.166 5.842,58.166 5.842,56.642 v1(5.842,54.61) ; -22.606,68.072 -18.288,68.072 -17.018,68.072 -17.018,64.77 -8.382,64.77 -8.382,61.468 -0.508,61.468 -0.508,69.088 1.016,69.088 5.842,69.088 ; -22.606,70.612 -20.32,70.612 -20.32,80.264 -16.764,80.264 -16.764,85.598 -12.192,85.598 -9.652,85.598 -8.128,85.598 -8.128,83.058 -3.81,83.058 -3.81,81.534 v1(-3.81,79.502) ; -22.098,102.87 -22.098,99.568 -16.256,99.568 -16.256,87.122 v1(-6.35,87.122) ; -18.564,45.72 -7.112,45.72 ; v1(-17.78,78.232) -17.78,74.168 ; v2(-17.526,95.25) -20.828,95.25 -33.782,95.25 ; -17.018,102.87 -14.986,102.87 -14.986,97.79 -14.986,89.408 6.35,89.408 6.35,88.138 ; -13.97,31.75 -12.446,32.512 -2.032,32.512 -2.032,34.544 -2.032,37.338 -3.302,38.608 -3.302,39.624 ; -13.208,68.072 -15.24,68.072 -15.24,72.136 -17.78,72.136 -17.78,73.152 -17.78,74.168 ; -12.192,60.96 -12.192,58.166 -12.192,55.372 -12.192,52.832 ; -10.668,76.2 -10.668,68.072 ; -8.128,68.072 -3.048,68.072 -3.048,66.04 ; -4.572,34.544 -6.604,34.544 -6.604,45.212 -7.112,45.72 ; v1(-3.81,87.122) -3.81,85.344 -3.81,84.582 8.128,84.582 ; -3.048,63.5 -5.842,63.5 -5.842,66.04 -10.668,66.04 -10.668,68.072 ; -2.794,48.514 -2.794,43.18 2.286,38.1 2.286,34.798 6.89,34.798 6.89,31.398 ; -2.794,71.882 -2.794,70.358 -10.668,70.358 -10.668,68.072 ; -2.794,74.422 -2.794,77.216 -6.604,77.216 -8.636,77.216 -8.636,78.486 -13.208,78.486 -13.208,74.168 -17.78,74.168 ; 0.276,45.72 3.81,42.164 ; 4.572,46.736 4.572,47.244 4.572,48.514 -4.318,48.514 -7.112,45.72 ; v1(5.842,62.23) 5.842,60.452 5.842,59.69 17.78,59.69 ; v1(5.842,66.802) 5.842,68.834 ; v1(5.842,74.422) 5.842,72.644 5.842,71.882 17.78,71.882 ; 6.604,84.582 11.176,84.582 11.176,71.882 ; 6.89,38.198 8.226,38.198 10.414,40.386 10.414,44.704 10.414,46.482 10.16,46.736 7.112,46.736 ; 7.366,42.164 3.81,42.164 ; 10.89,36.498 13.208,38.862 13.208,42.164 ; 13.716,59.69 19.812,59.69 ; v1(16.002,74.422) 18.288,74.422 v1(18.288,78.232) ; 16.256,71.882 19.812,71.882 19.812,59.69 ; -12.192,52.832 0.762,52.832 0.762,51.816 19.812,51.816 19.812,59.69 ; 3.81,42.164 3.81,40.64 3.81,42.164
  BottomLayer w0.762: -83.058,56.419 -78.613,56.419 ; -83.058,58.959 -78.613,58.959 ; -83.058,64.039 -83.058,62.134 -82.423,61.499 -78.613,61.499 ; -83.058,66.579 -78.613,66.579 ; -81.153,69.754 -78.613,69.754 -76.708,67.849 -76.708,64.674 -77.343,64.039 -78.613,64.039 ; -81.153,72.294 -78.74,74.676 ; -78.613,53.879 -77.978,53.879 ; -75.946,53.848 -75.946,62.484 -75.184,63.246 -75.184,70.008 ; -75.438,72.294 -74.168,72.294 -72.898,71.024 -72.898,68.484 -73.533,67.849
  BottomLayer w0.8: -78.74,74.676 -72.136,74.676 -70.866,73.66 -70.866,66.802 -70.993,66.325
  BottomLayer w1: -70.993,64.039 -68.834,64.008 -68.834,71.12 ; -68.834,66.802 -62.992,66.802 ; -43.344,97.536 -43.18,97.79 -43.18,101.092 -42.926,102.87 ; -38.1,102.616 -37.846,101.092 -37.936,97.536 ; -17.272,55.372 -14.732,55.372 ; -17.272,58.166 -14.732,58.166 ; -17.272,60.96 -14.732,60.96 ; -4.064,26.416 3.81,26.416 3.81,29.21
  other v1: 3.302,54.61 16.002,62.23 3.302,66.802 16.002,66.802 6.35,79.502 6.35,87.122
  other v3: -74.676,86.36

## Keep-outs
KeepOutLayer:
  lines w0.8: -13.462,90.932 24.892,90.932 24.892,19.558 -86.106,19.558 -86.106,91.186 -57.658,91.186 -57.658,106.172 -13.462,106.172 -13.462,91.186

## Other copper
TopLayer:
  rectangle: -11.684,33.02 -7.112,39.878
  rectangle: -4.572,48.26 1.524,51.054
  rectangle: -17.018,38.862 -6.096,43.18
  rectangle: -16.256,42.926 -2.54,49.784
  rectangle: 19.812,44.704 24.384,51.562
  rectangle: 15.24,26.162 24.384,45.466
  rectangle: 7.112,20.066 24.384,28.194
  rectangle: -24.384,30.734 -17.018,42.926
  rectangle: -50.038,55.626 -41.91,63.754
  rectangle: -85.852,81.788 -73.914,90.932
  rectangle: -74.168,87.122 -56.134,90.932
  rectangle: -85.852,70.612 -84.074,82.296
  rectangle: -56.134,86.36 -18.034,88.138
  rectangle: -59.69,81.026 -57.15,87.376
  rectangle: -57.658,90.932 -56.642,105.664
  rectangle: -56.642,94.742 -54.356,100.33
  rectangle: -34.544,99.314 -29.972,105.41
  rectangle: -27.432,30.734 -23.622,44.704
  rectangle: -28.194,50.546 -24.638,73.66
  rectangle: -26.924,46.736 -24.638,50.8
  rectangle: -30.988,51.816 -27.94,53.34
  rectangle: 13.462,80.264 24.384,90.424
  rectangle: 22.606,50.8 24.384,80.518
  rectangle: -4.572,20.066 1.524,24.13
  rectangle: 1.016,20.066 7.112,21.082
  rectangle: -12.954,20.066 -4.318,21.082
  rectangle: -21.336,20.066 -9.398,28.956
  rectangle: -11.684,28.956 -9.398,33.274
  rectangle: -76.708,34.798 -25.908,44.704
  rectangle: -78.994,36.576 -76.2,44.704
  rectangle: -26.924,26.416 -17.018,30.988
  rectangle: -54.102,29.464 -26.416,35.306
  rectangle: 1.524,49.784 17.272,51.054
  rectangle: 9.144,48.006 17.272,50.038
  rectangle: 10.16,44.196 15.24,45.466
BottomLayer:
  rectangle: -18.288,39.116 -11.684,42.926
  rectangle: -11.684,34.036 -6.35,43.434
  rectangle: 9.144,48.26 15.24,50.546
  rectangle: -17.018,42.672 -2.794,51.308
  rectangle: 7.112,20.066 14.986,28.194
  rectangle: 14.986,20.066 24.384,50.546
  region: -21.082,37.084 -21.082,36.068 -13.462,36.068 -13.462,37.084
  region: -2.794,49.53 -2.794,48.514 4.826,48.514 4.826,49.53
  region: 0.508,35.052 0.508,31.242 8.89,31.242 8.89,35.052
  rectangle: -68.834,58.674 -63.5,67.056
  rectangle: -64.77,63.5 -62.23,67.056
  rectangle: -66.802,66.802 -62.23,72.136
  rectangle: -62.23,69.088 -60.198,72.136
  rectangle: -68.072,45.974 -63.754,55.118
  rectangle: -70.612,43.688 -52.324,46.736
  rectangle: -77.216,87.122 -56.134,90.932
  rectangle: -59.69,75.946 -56.134,87.376
  rectangle: -77.216,81.788 -74.168,88.138
  rectangle: -76.2,75.946 -63.754,78.994
  rectangle: -68.326,76.962 -65.278,83.058
  rectangle: -85.852,82.042 -77.216,90.932
  rectangle: -85.852,70.104 -84.074,82.804
  rectangle: -54.61,43.688 -51.054,54.102
  rectangle: -64.77,50.546 -54.102,52.324
  rectangle: -55.118,50.546 -39.624,64.262
  rectangle: -51.308,43.688 -43.688,51.054
  rectangle: -56.388,75.692 -47.498,78.994
  rectangle: -51.308,63.754 -47.498,76.2
  rectangle: -30.226,30.734 -20.574,42.418
  rectangle: -69.596,30.734 -28.702,43.942
  rectangle: -43.942,41.656 -20.574,46.99
  rectangle: -36.322,70.866 -32.004,78.74
  rectangle: -28.194,52.578 -24.638,73.66
  rectangle: -27.686,46.99 -25.146,53.086
  rectangle: -20.574,30.988 -17.018,49.276
  rectangle: -47.752,64.008 -43.18,76.708
  rectangle: -43.434,62.23 -32.004,74.168
  rectangle: -39.624,50.546 -32.004,57.404
  rectangle: -39.878,56.134 -36.83,64.008
  rectangle: -34.29,56.896 -32.004,63.5
  rectangle: -32.004,50.546 -27.686,53.34
  rectangle: -56.388,85.09 -18.288,88.138
  rectangle: -37.338,80.772 -35.814,90.932
  rectangle: -27.178,81.026 -25.654,90.932
  rectangle: -47.498,81.534 -45.974,90.932
  rectangle: -46.228,99.568 -45.212,105.664
  rectangle: -57.404,99.568 -56.388,105.664
  rectangle: -56.896,94.742 -54.102,99.822
  rectangle: -34.544,99.314 -29.972,105.41
  rectangle: -85.598,20.066 -69.596,46.736
  rectangle: -55.372,20.066 -37.084,25.908
  rectangle: -22.606,20.066 -17.272,31.242
  rectangle: -20.574,20.066 -9.398,28.956
  rectangle: -11.176,28.448 -4.064,31.496
  rectangle: -9.652,20.066 7.366,21.082
  rectangle: -4.572,20.828 1.524,24.13
  rectangle: -85.598,46.482 -80.772,54.102
  rectangle: -74.422,46.736 -73.152,61.214
  rectangle: -76.708,46.482 -74.168,52.07
  rectangle: -73.914,61.214 -73.152,64.77
  rectangle: -56.896,25.908 -37.084,32.004
  rectangle: -37.338,27.178 -33.274,30.988
  rectangle: -26.924,26.416 -21.59,30.988
  rectangle: 21.336,50.292 24.384,90.424
  rectangle: 12.7,80.264 22.352,90.424
  rectangle: 9.144,85.852 13.208,90.424

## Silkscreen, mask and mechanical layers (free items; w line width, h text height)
TopOverlay:
  lines w0.254: -8.128,77.978 -8.128,88.646 8.89,88.646 8.89,77.978 -8.128,77.978 ; -4.064,26.416 3.81,23.622 3.81,28.956 -4.064,26.416 ; 1.524,53.086 1.524,63.754 18.542,63.754 18.542,53.086 1.524,53.086 ; 1.524,65.278 1.524,75.946 18.542,75.946 18.542,65.278 1.524,65.278
  text "IN1" at -55.118,99.568 h0.7
  text "IN2" at -49.53,99.568 h0.7
  text "+12V" at -44.45,99.568 h0.7
  text "IN3" at -38.862,99.568 h0.7
  text "GND" at -33.528,99.568 h0.7
  text "NC" at -28.194,99.568 h0.7
  text "NO" at -23.114,99.568 h0.7
  text "COMM" at -18.542,99.568 h0.7
  text "NO" at -1.524,88.392 h1 r270
  text "REL1" at -6.858,84.582 h1 r270
  text "NC" at -1.27,80.264 h1 r270
  text "NO" at 20.574,77.47 h1
  text "NO" at 8.128,75.692 h1 r270
  text "UCC" at -57.658,75.184 h0.7 r90
  text "MOSI" at -55.118,75.184 h0.7 r90
  text "GND" at -52.578,75.184 h0.7 r90
  text "REL2" at 2.794,71.882 h1 r270
  text "NC" at 8.382,67.564 h1 r270
  text "SCK" at -55.118,67.31 h0.7 r90
  text "RES" at -52.578,67.31 h0.7 r90
  text "MISO" at -57.658,66.548 h0.7 r90
  text "REL3" at 2.794,59.69 h1 r270
  text "PE.0" at -34.29,59.436 h0.7
  text "NO" at -5.334,57.404 h1 r270
  text "PD.3" at -56.388,56.896 h0.7
  text "RFID Door Locker" at -58.674,41.91 h2
  text "www.frigg-tronic.pl" at -61.722,39.116 h2
  text "-" at -18.796,35.814 h2
  text "U6" at 17.272,35.052 h1.2
  text "RFID Reader" at -70.358,31.242 h1.5
  text "PC" at -37.084,30.734 h1.5
  text "+" at -18.542,30.734 h2
  text "PR1" at -6.096,28.702 h1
